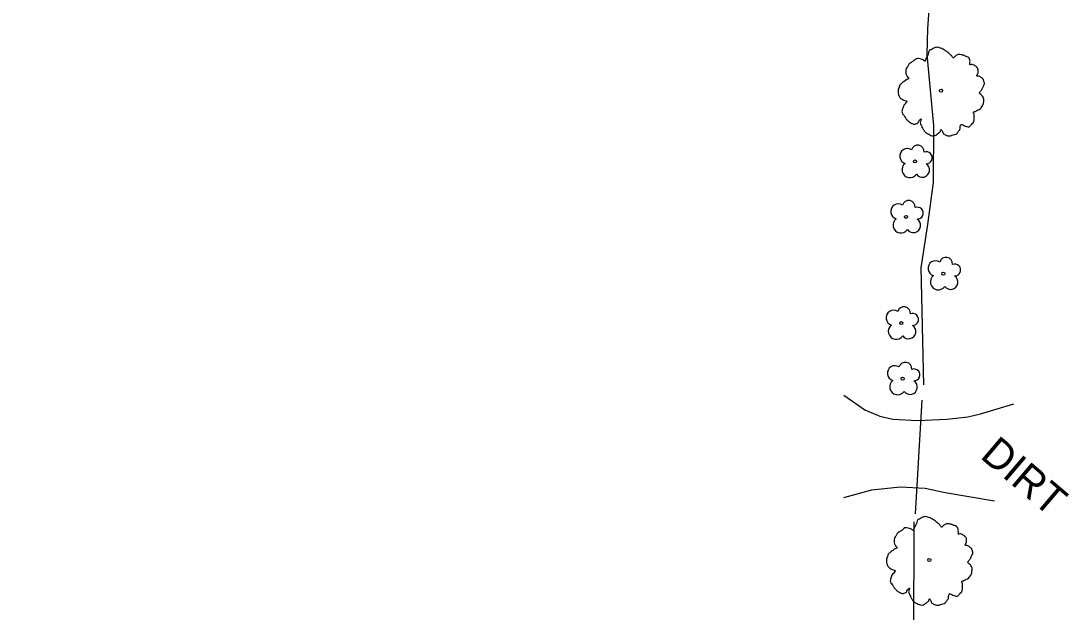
# Model space of a CAD drawing. Extents: x 2076109 to 2080761, y 592812 to 596750.
# Drawn here: x 2076804.3 to 2076979, y 595772.6 to 595871.1 of the extents above; entities that cross this region are included whole.
import ezdxf

# ---------------------------------------------------------------- set-up
doc = ezdxf.new("R2010")
doc.units = 0
for name, color, linetype in [('RD_EX_DR_Pipe', 7, 'Continuous'), ('RD_EX_Driveway', 7, 'Continuous'), ('RD_EX_Driveway_txCode', 7, 'Continuous'), ('RD_EX_H2O', 7, 'Continuous'), ('RD_EX_VEG', 7, 'Continuous')]:
    doc.layers.add(name, color=color, linetype=linetype)

msp = doc.modelspace()

# ---------------------------------------------------------------- linework, layer by layer
at = {"layer": 'RD_EX_DR_Pipe'}
msp.add_line((2076954.49, 595807.87), (2076953.41, 595788.91), dxfattribs=at)
msp.add_line((2076954.49, 595807.87), (2076953.41, 595788.91), dxfattribs=at)
at = {"layer": 'RD_EX_Driveway'}
for points in [[(2076941.49, 595808.73), (2076944.98, 595806.27), (2076947.48, 595805.2), (2076949.66, 595804.73), (2076953.82, 595804.47), (2076958.66, 595804.69), (2076962.15, 595805.1), (2076964.3, 595805.62), (2076969.85, 595807.26)], [(2076941.49, 595808.73), (2076944.98, 595806.27), (2076947.48, 595805.2), (2076949.66, 595804.73), (2076953.82, 595804.47), (2076958.66, 595804.69), (2076962.15, 595805.1), (2076964.3, 595805.62), (2076969.85, 595807.26)], [(2076941.5, 595791.66), (2076946.18, 595792.94), (2076950.88, 595793.42), (2076955.05, 595793.23), (2076958.38, 595792.48), (2076966.62, 595791.1)], [(2076941.5, 595791.66), (2076946.18, 595792.94), (2076950.88, 595793.42), (2076955.05, 595793.23), (2076958.38, 595792.48), (2076966.62, 595791.1)]]:
    msp.add_lwpolyline(points, dxfattribs=at)
at = {"layer": 'RD_EX_H2O'}
for points in [[(2076956.27, 595881.28), (2076955.47, 595869.82), (2076955.32, 595865.52), (2076956.46, 595853.67), (2076956.38, 595844.15), (2076955.42, 595837.17), (2076954.34, 595829.92), (2076954.75, 595810.44)], [(2076956.27, 595881.28), (2076955.47, 595869.82), (2076955.32, 595865.52), (2076956.46, 595853.67), (2076956.38, 595844.15), (2076955.42, 595837.17), (2076954.34, 595829.92), (2076954.75, 595810.44)], [(2076953.18, 595787.61), (2076953.11, 595768.11), (2076952.56, 595756.13), (2076952.64, 595748.41), (2076952.76, 595745.08), (2076953.8, 595742.99), (2076953.36, 595730.22), (2076953.03, 595725.71), (2076951.39, 595721.38), (2076949.37, 595718.3), (2076942.5, 595711.04), (2076932.67, 595698.19), (2076918.85, 595680.89), (2076905.91, 595664.86), (2076891.97, 595647.71), (2076883.67, 595637.84), (2076877.03, 595627.21), (2076865.95, 595614.44), (2076853.87, 595600.18), (2076844.92, 595587.87), (2076832.87, 595574.13), (2076822.92, 595563.08), (2076804.28, 595545.77)], [(2076953.18, 595787.61), (2076953.11, 595768.11), (2076952.56, 595756.13), (2076952.64, 595748.41), (2076952.76, 595745.08), (2076953.8, 595742.99), (2076953.36, 595730.22), (2076953.03, 595725.71), (2076951.39, 595721.38), (2076949.37, 595718.3), (2076942.5, 595711.04), (2076932.67, 595698.19), (2076918.85, 595680.89), (2076905.91, 595664.86), (2076891.97, 595647.71), (2076883.67, 595637.84), (2076877.03, 595627.21), (2076865.95, 595614.44), (2076853.87, 595600.18), (2076844.92, 595587.87), (2076832.87, 595574.13), (2076822.92, 595563.08), (2076804.28, 595545.77)]]:
    msp.add_lwpolyline(points, dxfattribs=at)
at = {"layer": 'RD_EX_VEG'}
for centre, radius in [((2076957.7, 595859.47), 0.25), ((2076957.7, 595859.47), 0.25), ((2076957.67, 595859.46), 0.0001), ((2076957.67, 595859.46), 0.0001), ((2076953.36, 595847.67), 0.25), ((2076953.36, 595847.67), 0.25), ((2076951.86, 595838.43), 0.25), ((2076951.86, 595838.43), 0.25), ((2076958.08, 595828.96), 0.25), ((2076958.08, 595828.96), 0.25), ((2076951.07, 595820.72), 0.25), ((2076951.07, 595820.72), 0.25), ((2076951.3, 595811.47), 0.25), ((2076951.3, 595811.47), 0.25), ((2076955.75, 595781.24), 0.25), ((2076955.75, 595781.24), 0.25), ((2076955.73, 595781.24), 0.0001), ((2076955.73, 595781.24), 0.0001)]:
    msp.add_circle(centre, radius, dxfattribs=at)
for centre, radius, start, end in [((2076952.06, 595848.56), 1.26, 56.0792, 254.3614), ((2076952.06, 595848.56), 1.26, 56.0792, 254.3614), ((2076953.81, 595849.31), 1.08, 354.6037, 164.3834), ((2076953.81, 595849.31), 1.08, 354.6037, 164.3834), ((2076955.25, 595848.29), 0.995, 268.39, 111.6741), ((2076955.25, 595848.29), 0.995, 268.39, 111.6741), ((2076952.51, 595846.29), 1.32, 126.51, 325.3863), ((2076952.51, 595846.29), 1.32, 126.51, 325.3863), ((2076954.58, 595846.26), 1.22, 216.1941, 57.732), ((2076954.58, 595846.26), 1.22, 216.1941, 57.732), ((2076950.57, 595839.33), 1.26, 56.0792, 254.3614), ((2076950.57, 595839.33), 1.26, 56.0792, 254.3614), ((2076952.31, 595840.08), 1.08, 354.6037, 164.3834), ((2076952.31, 595840.08), 1.08, 354.6037, 164.3834), ((2076953.76, 595839.05), 0.995, 268.39, 111.6741), ((2076953.76, 595839.05), 0.995, 268.39, 111.6741), ((2076951.01, 595837.06), 1.32, 126.51, 325.3863), ((2076951.01, 595837.06), 1.32, 126.51, 325.3863), ((2076953.08, 595837.03), 1.22, 216.1941, 57.732), ((2076953.08, 595837.03), 1.22, 216.1941, 57.732), ((2076956.79, 595829.86), 1.26, 56.0792, 254.3614), ((2076956.79, 595829.86), 1.26, 56.0792, 254.3614), ((2076958.54, 595830.61), 1.08, 354.6037, 164.3834), ((2076958.54, 595830.61), 1.08, 354.6037, 164.3834), ((2076959.98, 595829.58), 0.995, 268.39, 111.6741), ((2076959.98, 595829.58), 0.995, 268.39, 111.6741), ((2076957.24, 595827.59), 1.32, 126.51, 325.3863), ((2076957.24, 595827.59), 1.32, 126.51, 325.3863), ((2076959.3, 595827.56), 1.22, 216.1941, 57.732), ((2076959.3, 595827.56), 1.22, 216.1941, 57.732), ((2076951.53, 595822.37), 1.08, 354.6037, 164.3834), ((2076951.53, 595822.37), 1.08, 354.6037, 164.3834), ((2076949.78, 595821.61), 1.26, 56.0792, 254.3614), ((2076949.78, 595821.61), 1.26, 56.0792, 254.3614), ((2076952.97, 595821.34), 0.995, 268.39, 111.6741), ((2076952.97, 595821.34), 0.995, 268.39, 111.6741), ((2076950.23, 595819.34), 1.32, 126.51, 325.3863), ((2076950.23, 595819.34), 1.32, 126.51, 325.3863), ((2076952.29, 595819.32), 1.22, 216.1941, 57.732), ((2076952.29, 595819.32), 1.22, 216.1941, 57.732), ((2076950.01, 595812.37), 1.26, 56.0792, 254.3614), ((2076950.01, 595812.37), 1.26, 56.0792, 254.3614), ((2076951.76, 595813.12), 1.08, 354.6037, 164.3834), ((2076951.76, 595813.12), 1.08, 354.6037, 164.3834), ((2076953.2, 595812.09), 0.995, 268.39, 111.6741), ((2076953.2, 595812.09), 0.995, 268.39, 111.6741), ((2076950.46, 595810.1), 1.32, 126.51, 325.3863), ((2076950.46, 595810.1), 1.32, 126.51, 325.3863), ((2076952.53, 595810.07), 1.22, 216.1941, 57.732), ((2076952.53, 595810.07), 1.22, 216.1941, 57.732)]:
    msp.add_arc(centre, radius, start, end, dxfattribs=at)
for points in [[(2076962.44, 595864.84), (2076962.23, 595865.06), (2076961.91, 595865.19), (2076961.66, 595865.28), (2076961.44, 595865.36), (2076961.2, 595865.43), (2076960.86, 595865.49), (2076960.56, 595865.49), (2076960.3, 595865.38), (2076960.12, 595865.24), (2076959.9, 595865.06), (2076959.79, 595864.93), (2076959.68, 595864.99), (2076959.58, 595865.11), (2076959.44, 595865.33), (2076959.25, 595865.49), (2076959.06, 595865.65), (2076958.78, 595865.86), (2076958.51, 595866.08), (2076958.27, 595866.22), (2076957.99, 595866.4), (2076957.62, 595866.54), (2076957.27, 595866.68), (2076956.88, 595866.68), (2076956.39, 595866.48), (2076956.06, 595866.29), (2076955.79, 595866.2), (2076955.61, 595865.76), (2076955.52, 595865.38), (2076955.41, 595865.21), (2076955.19, 595864.84), (2076955.12, 595864.6), (2076955.08, 595864.37), (2076955.01, 595864.4), (2076954.69, 595864.61), (2076954.4, 595864.72), (2076953.93, 595864.83), (2076953.61, 595864.8), (2076953.33, 595864.62), (2076953.08, 595864.37), (2076952.88, 595864.28), (2076952.64, 595864.12), (2076952.57, 595864.08), (2076952.32, 595863.86), (2076952.11, 595863.46), (2076951.9, 595863.17), (2076951.85, 595862.92), (2076951.85, 595862.69), (2076951.82, 595862.39), (2076951.98, 595861.96), (2076952.17, 595861.67), (2076952.3, 595861.52), (2076951.84, 595861.25), (2076951.58, 595861.02), (2076951.23, 595860.8), (2076951.18, 595860.74), (2076950.83, 595860.41), (2076950.74, 595860.07), (2076950.55, 595859.73), (2076950.54, 595859.45), (2076950.55, 595859.04), (2076950.65, 595858.66), (2076950.95, 595858.24), (2076951.28, 595858), (2076951.83, 595857.76), (2076952.07, 595857.66), (2076951.93, 595857.54), (2076951.71, 595857.24), (2076951.43, 595856.91), (2076951.34, 595856.57), (2076951.24, 595856.29), (2076951.19, 595856.01), (2076951.29, 595855.63), (2076951.55, 595855.31), (2076951.77, 595854.92), (2076952.07, 595854.57), (2076952.43, 595854.23), (2076952.99, 595853.95), (2076953.28, 595853.87), (2076953.47, 595853.94), (2076953.86, 595854.1), (2076953.97, 595854.3), (2076954.38, 595854.74), (2076954.34, 595854.54), (2076954.24, 595854.16), (2076954.43, 595853.61), (2076954.62, 595853.22), (2076954.89, 595852.8), (2076955.07, 595852.55), (2076955.48, 595852.29), (2076955.81, 595852.11), (2076956.18, 595851.96), (2076956.58, 595851.98), (2076956.9, 595852.07), (2076957.11, 595852.25), (2076957.41, 595852.49), (2076957.56, 595852.59)], [(2076962.44, 595864.84), (2076962.23, 595865.06), (2076961.91, 595865.19), (2076961.66, 595865.28), (2076961.44, 595865.36), (2076961.2, 595865.43), (2076960.86, 595865.49), (2076960.56, 595865.49), (2076960.3, 595865.38), (2076960.12, 595865.24), (2076959.9, 595865.06), (2076959.79, 595864.93), (2076959.68, 595864.99), (2076959.58, 595865.11), (2076959.44, 595865.33), (2076959.25, 595865.49), (2076959.06, 595865.65), (2076958.78, 595865.86), (2076958.51, 595866.08), (2076958.27, 595866.22), (2076957.99, 595866.4), (2076957.62, 595866.54), (2076957.27, 595866.68), (2076956.88, 595866.68), (2076956.39, 595866.48), (2076956.06, 595866.29), (2076955.79, 595866.2), (2076955.61, 595865.76), (2076955.52, 595865.38), (2076955.41, 595865.21), (2076955.19, 595864.84), (2076955.12, 595864.6), (2076955.08, 595864.37), (2076955.01, 595864.4), (2076954.69, 595864.61), (2076954.4, 595864.72), (2076953.93, 595864.83), (2076953.61, 595864.8), (2076953.33, 595864.62), (2076953.08, 595864.37), (2076952.88, 595864.28), (2076952.64, 595864.12), (2076952.57, 595864.08), (2076952.32, 595863.86), (2076952.11, 595863.46), (2076951.9, 595863.17), (2076951.85, 595862.92), (2076951.85, 595862.69), (2076951.82, 595862.39), (2076951.98, 595861.96), (2076952.17, 595861.67), (2076952.3, 595861.52), (2076951.84, 595861.25), (2076951.58, 595861.02), (2076951.23, 595860.8), (2076951.18, 595860.74), (2076950.83, 595860.41), (2076950.74, 595860.07), (2076950.55, 595859.73), (2076950.54, 595859.45), (2076950.55, 595859.04), (2076950.65, 595858.66), (2076950.95, 595858.24), (2076951.28, 595858), (2076951.83, 595857.76), (2076952.07, 595857.66), (2076951.93, 595857.54), (2076951.71, 595857.24), (2076951.43, 595856.91), (2076951.34, 595856.57), (2076951.24, 595856.29), (2076951.19, 595856.01), (2076951.29, 595855.63), (2076951.55, 595855.31), (2076951.77, 595854.92), (2076952.07, 595854.57), (2076952.43, 595854.23), (2076952.99, 595853.95), (2076953.28, 595853.87), (2076953.47, 595853.94), (2076953.86, 595854.1), (2076953.97, 595854.3), (2076954.38, 595854.74), (2076954.34, 595854.54), (2076954.24, 595854.16), (2076954.43, 595853.61), (2076954.62, 595853.22), (2076954.89, 595852.8), (2076955.07, 595852.55), (2076955.48, 595852.29), (2076955.81, 595852.11), (2076956.18, 595851.96), (2076956.58, 595851.98), (2076956.9, 595852.07), (2076957.11, 595852.25), (2076957.41, 595852.49), (2076957.56, 595852.59)], [(2076957.56, 595852.59), (2076957.62, 595852.77), (2076957.74, 595852.99), (2076957.78, 595852.92), (2076957.89, 595852.77), (2076958.01, 595852.5), (2076958.14, 595852.3), (2076958.4, 595852.11), (2076958.67, 595852), (2076959.19, 595851.92), (2076959.71, 595852.11), (2076960.18, 595852.23), (2076960.45, 595852.43), (2076960.56, 595852.63), (2076960.86, 595853.03), (2076960.87, 595853.35), (2076960.91, 595853.48), (2076961.1, 595853.85), (2076961.18, 595853.84), (2076961.43, 595853.7), (2076961.79, 595853.55), (2076962.08, 595853.47), (2076962.37, 595853.46), (2076962.57, 595853.58), (2076962.81, 595853.9), (2076963.11, 595854.17), (2076963.15, 595854.33), (2076963.17, 595854.51), (2076963.24, 595854.71), (2076963.22, 595854.92), (2076963.25, 595855.1), (2076963.23, 595855.24), (2076963.24, 595855.44), (2076963.18, 595855.65), (2076963.1, 595855.78), (2076963.16, 595855.93), (2076963.4, 595855.99), (2076963.51, 595856.03), (2076963.67, 595856.18), (2076964.07, 595856.31), (2076964.37, 595856.58), (2076964.6, 595856.93), (2076964.74, 595857.18), (2076964.81, 595857.48), (2076964.82, 595857.8), (2076964.84, 595858.02), (2076964.78, 595858.22), (2076964.62, 595858.53), (2076964.46, 595858.73), (2076964.19, 595858.96), (2076964.07, 595859.12), (2076964.12, 595859.15), (2076964.22, 595859.26), (2076964.4, 595859.47), (2076964.63, 595859.86), (2076964.84, 595860.34), (2076964.86, 595860.36), (2076964.94, 595860.61), (2076964.9, 595860.91), (2076964.83, 595861.1), (2076964.76, 595861.33), (2076964.59, 595861.51), (2076964.36, 595861.7), (2076964.12, 595861.84), (2076963.9, 595861.89), (2076963.69, 595861.91), (2076963.73, 595862.07), (2076963.85, 595862.37), (2076963.9, 595862.51), (2076963.9, 595862.74), (2076963.86, 595863.04), (2076963.6, 595863.43), (2076963.08, 595863.78), (2076962.72, 595863.82), (2076962.49, 595863.78), (2076962.53, 595863.91), (2076962.51, 595864.19), (2076962.55, 595864.39), (2076962.49, 595864.6), (2076962.44, 595864.77), (2076962.4, 595864.87)], [(2076957.56, 595852.59), (2076957.62, 595852.77), (2076957.74, 595852.99), (2076957.78, 595852.92), (2076957.89, 595852.77), (2076958.01, 595852.5), (2076958.14, 595852.3), (2076958.4, 595852.11), (2076958.67, 595852), (2076959.19, 595851.92), (2076959.71, 595852.11), (2076960.18, 595852.23), (2076960.45, 595852.43), (2076960.56, 595852.63), (2076960.86, 595853.03), (2076960.87, 595853.35), (2076960.91, 595853.48), (2076961.1, 595853.85), (2076961.18, 595853.84), (2076961.43, 595853.7), (2076961.79, 595853.55), (2076962.08, 595853.47), (2076962.37, 595853.46), (2076962.57, 595853.58), (2076962.81, 595853.9), (2076963.11, 595854.17), (2076963.15, 595854.33), (2076963.17, 595854.51), (2076963.24, 595854.71), (2076963.22, 595854.92), (2076963.25, 595855.1), (2076963.23, 595855.24), (2076963.24, 595855.44), (2076963.18, 595855.65), (2076963.1, 595855.78), (2076963.16, 595855.93), (2076963.4, 595855.99), (2076963.51, 595856.03), (2076963.67, 595856.18), (2076964.07, 595856.31), (2076964.37, 595856.58), (2076964.6, 595856.93), (2076964.74, 595857.18), (2076964.81, 595857.48), (2076964.82, 595857.8), (2076964.84, 595858.02), (2076964.78, 595858.22), (2076964.62, 595858.53), (2076964.46, 595858.73), (2076964.19, 595858.96), (2076964.07, 595859.12), (2076964.12, 595859.15), (2076964.22, 595859.26), (2076964.4, 595859.47), (2076964.63, 595859.86), (2076964.84, 595860.34), (2076964.86, 595860.36), (2076964.94, 595860.61), (2076964.9, 595860.91), (2076964.83, 595861.1), (2076964.76, 595861.33), (2076964.59, 595861.51), (2076964.36, 595861.7), (2076964.12, 595861.84), (2076963.9, 595861.89), (2076963.69, 595861.91), (2076963.73, 595862.07), (2076963.85, 595862.37), (2076963.9, 595862.51), (2076963.9, 595862.74), (2076963.86, 595863.04), (2076963.6, 595863.43), (2076963.08, 595863.78), (2076962.72, 595863.82), (2076962.49, 595863.78), (2076962.53, 595863.91), (2076962.51, 595864.19), (2076962.55, 595864.39), (2076962.49, 595864.6), (2076962.44, 595864.77), (2076962.4, 595864.87)], [(2076960.5, 595786.62), (2076960.28, 595786.83), (2076959.97, 595786.97), (2076959.72, 595787.05), (2076959.5, 595787.14), (2076959.26, 595787.21), (2076958.92, 595787.27), (2076958.62, 595787.26), (2076958.36, 595787.16), (2076958.18, 595787.02), (2076957.96, 595786.84), (2076957.85, 595786.71), (2076957.74, 595786.77), (2076957.64, 595786.88), (2076957.5, 595787.1), (2076957.31, 595787.26), (2076957.11, 595787.43), (2076956.83, 595787.63), (2076956.57, 595787.86), (2076956.32, 595788), (2076956.04, 595788.17), (2076955.68, 595788.32), (2076955.33, 595788.45), (2076954.94, 595788.46), (2076954.44, 595788.26), (2076954.12, 595788.07), (2076953.84, 595787.98), (2076953.67, 595787.54), (2076953.57, 595787.16), (2076953.46, 595786.99), (2076953.24, 595786.62), (2076953.18, 595786.38), (2076953.14, 595786.15), (2076953.07, 595786.18), (2076952.75, 595786.38), (2076952.46, 595786.5), (2076951.99, 595786.6), (2076951.67, 595786.58), (2076951.38, 595786.4), (2076951.14, 595786.15), (2076950.93, 595786.06), (2076950.7, 595785.9), (2076950.63, 595785.86), (2076950.38, 595785.64), (2076950.17, 595785.23), (2076949.96, 595784.95), (2076949.91, 595784.7), (2076949.91, 595784.47), (2076949.88, 595784.16), (2076950.04, 595783.73), (2076950.22, 595783.45), (2076950.36, 595783.3), (2076949.9, 595783.03), (2076949.64, 595782.8), (2076949.28, 595782.57), (2076949.23, 595782.52), (2076948.89, 595782.19), (2076948.79, 595781.84), (2076948.61, 595781.51), (2076948.59, 595781.22), (2076948.61, 595780.82), (2076948.71, 595780.44), (2076949.01, 595780.02), (2076949.33, 595779.78), (2076949.88, 595779.54), (2076950.12, 595779.43), (2076949.99, 595779.32), (2076949.77, 595779.01), (2076949.49, 595778.69), (2076949.39, 595778.35), (2076949.29, 595778.07), (2076949.24, 595777.78), (2076949.35, 595777.4), (2076949.6, 595777.09), (2076949.83, 595776.7), (2076950.12, 595776.35), (2076950.49, 595776.01), (2076951.04, 595775.73), (2076951.33, 595775.65), (2076951.52, 595775.72), (2076951.92, 595775.87), (2076952.02, 595776.08), (2076952.43, 595776.52), (2076952.39, 595776.32), (2076952.3, 595775.94), (2076952.49, 595775.39), (2076952.68, 595775), (2076952.94, 595774.57), (2076953.12, 595774.32), (2076953.53, 595774.07), (2076953.87, 595773.89), (2076954.23, 595773.74), (2076954.64, 595773.75), (2076954.95, 595773.85), (2076955.17, 595774.03), (2076955.47, 595774.26), (2076955.62, 595774.36)], [(2076960.5, 595786.62), (2076960.28, 595786.83), (2076959.97, 595786.97), (2076959.72, 595787.05), (2076959.5, 595787.14), (2076959.26, 595787.21), (2076958.92, 595787.27), (2076958.62, 595787.26), (2076958.36, 595787.16), (2076958.18, 595787.02), (2076957.96, 595786.84), (2076957.85, 595786.71), (2076957.74, 595786.77), (2076957.64, 595786.88), (2076957.5, 595787.1), (2076957.31, 595787.26), (2076957.11, 595787.43), (2076956.83, 595787.63), (2076956.57, 595787.86), (2076956.32, 595788), (2076956.04, 595788.17), (2076955.68, 595788.32), (2076955.33, 595788.45), (2076954.94, 595788.46), (2076954.44, 595788.26), (2076954.12, 595788.07), (2076953.84, 595787.98), (2076953.67, 595787.54), (2076953.57, 595787.16), (2076953.46, 595786.99), (2076953.24, 595786.62), (2076953.18, 595786.38), (2076953.14, 595786.15), (2076953.07, 595786.18), (2076952.75, 595786.38), (2076952.46, 595786.5), (2076951.99, 595786.6), (2076951.67, 595786.58), (2076951.38, 595786.4), (2076951.14, 595786.15), (2076950.93, 595786.06), (2076950.7, 595785.9), (2076950.63, 595785.86), (2076950.38, 595785.64), (2076950.17, 595785.23), (2076949.96, 595784.95), (2076949.91, 595784.7), (2076949.91, 595784.47), (2076949.88, 595784.16), (2076950.04, 595783.73), (2076950.22, 595783.45), (2076950.36, 595783.3), (2076949.9, 595783.03), (2076949.64, 595782.8), (2076949.28, 595782.57), (2076949.23, 595782.52), (2076948.89, 595782.19), (2076948.79, 595781.84), (2076948.61, 595781.51), (2076948.59, 595781.22), (2076948.61, 595780.82), (2076948.71, 595780.44), (2076949.01, 595780.02), (2076949.33, 595779.78), (2076949.88, 595779.54), (2076950.12, 595779.43), (2076949.99, 595779.32), (2076949.77, 595779.01), (2076949.49, 595778.69), (2076949.39, 595778.35), (2076949.29, 595778.07), (2076949.24, 595777.78), (2076949.35, 595777.4), (2076949.6, 595777.09), (2076949.83, 595776.7), (2076950.12, 595776.35), (2076950.49, 595776.01), (2076951.04, 595775.73), (2076951.33, 595775.65), (2076951.52, 595775.72), (2076951.92, 595775.87), (2076952.02, 595776.08), (2076952.43, 595776.52), (2076952.39, 595776.32), (2076952.3, 595775.94), (2076952.49, 595775.39), (2076952.68, 595775), (2076952.94, 595774.57), (2076953.12, 595774.32), (2076953.53, 595774.07), (2076953.87, 595773.89), (2076954.23, 595773.74), (2076954.64, 595773.75), (2076954.95, 595773.85), (2076955.17, 595774.03), (2076955.47, 595774.26), (2076955.62, 595774.36)], [(2076955.62, 595774.36), (2076955.68, 595774.55), (2076955.8, 595774.77), (2076955.84, 595774.7), (2076955.94, 595774.55), (2076956.07, 595774.28), (2076956.19, 595774.07), (2076956.46, 595773.88), (2076956.73, 595773.78), (2076957.25, 595773.7), (2076957.77, 595773.88), (2076958.24, 595774.01), (2076958.5, 595774.21), (2076958.61, 595774.41), (2076958.92, 595774.81), (2076958.93, 595775.13), (2076958.97, 595775.26), (2076959.15, 595775.63), (2076959.24, 595775.61), (2076959.48, 595775.47), (2076959.85, 595775.33), (2076960.14, 595775.24), (2076960.42, 595775.23), (2076960.63, 595775.35), (2076960.87, 595775.68), (2076961.16, 595775.95), (2076961.2, 595776.11), (2076961.23, 595776.29), (2076961.3, 595776.49), (2076961.28, 595776.7), (2076961.3, 595776.88), (2076961.29, 595777.02), (2076961.29, 595777.22), (2076961.24, 595777.43), (2076961.16, 595777.56), (2076961.22, 595777.71), (2076961.46, 595777.76), (2076961.56, 595777.81), (2076961.73, 595777.96), (2076962.13, 595778.08), (2076962.42, 595778.35), (2076962.66, 595778.71), (2076962.8, 595778.95), (2076962.86, 595779.26), (2076962.87, 595779.58), (2076962.89, 595779.79), (2076962.84, 595780), (2076962.67, 595780.31), (2076962.51, 595780.51), (2076962.25, 595780.73), (2076962.13, 595780.9), (2076962.18, 595780.92), (2076962.28, 595781.04), (2076962.45, 595781.25), (2076962.69, 595781.64), (2076962.9, 595782.12), (2076962.91, 595782.13), (2076963, 595782.39), (2076962.96, 595782.69), (2076962.89, 595782.88), (2076962.82, 595783.1), (2076962.64, 595783.28), (2076962.42, 595783.48), (2076962.17, 595783.62), (2076961.96, 595783.67), (2076961.74, 595783.69), (2076961.78, 595783.85), (2076961.9, 595784.14), (2076961.96, 595784.29), (2076961.96, 595784.52), (2076961.92, 595784.82), (2076961.66, 595785.21), (2076961.13, 595785.55), (2076960.77, 595785.6), (2076960.55, 595785.56), (2076960.59, 595785.69), (2076960.57, 595785.97), (2076960.6, 595786.17), (2076960.55, 595786.38), (2076960.5, 595786.55), (2076960.46, 595786.65)], [(2076955.62, 595774.36), (2076955.68, 595774.55), (2076955.8, 595774.77), (2076955.84, 595774.7), (2076955.94, 595774.55), (2076956.07, 595774.28), (2076956.19, 595774.07), (2076956.46, 595773.88), (2076956.73, 595773.78), (2076957.25, 595773.7), (2076957.77, 595773.88), (2076958.24, 595774.01), (2076958.5, 595774.21), (2076958.61, 595774.41), (2076958.92, 595774.81), (2076958.93, 595775.13), (2076958.97, 595775.26), (2076959.15, 595775.63), (2076959.24, 595775.61), (2076959.48, 595775.47), (2076959.85, 595775.33), (2076960.14, 595775.24), (2076960.42, 595775.23), (2076960.63, 595775.35), (2076960.87, 595775.68), (2076961.16, 595775.95), (2076961.2, 595776.11), (2076961.23, 595776.29), (2076961.3, 595776.49), (2076961.28, 595776.7), (2076961.3, 595776.88), (2076961.29, 595777.02), (2076961.29, 595777.22), (2076961.24, 595777.43), (2076961.16, 595777.56), (2076961.22, 595777.71), (2076961.46, 595777.76), (2076961.56, 595777.81), (2076961.73, 595777.96), (2076962.13, 595778.08), (2076962.42, 595778.35), (2076962.66, 595778.71), (2076962.8, 595778.95), (2076962.86, 595779.26), (2076962.87, 595779.58), (2076962.89, 595779.79), (2076962.84, 595780), (2076962.67, 595780.31), (2076962.51, 595780.51), (2076962.25, 595780.73), (2076962.13, 595780.9), (2076962.18, 595780.92), (2076962.28, 595781.04), (2076962.45, 595781.25), (2076962.69, 595781.64), (2076962.9, 595782.12), (2076962.91, 595782.13), (2076963, 595782.39), (2076962.96, 595782.69), (2076962.89, 595782.88), (2076962.82, 595783.1), (2076962.64, 595783.28), (2076962.42, 595783.48), (2076962.17, 595783.62), (2076961.96, 595783.67), (2076961.74, 595783.69), (2076961.78, 595783.85), (2076961.9, 595784.14), (2076961.96, 595784.29), (2076961.96, 595784.52), (2076961.92, 595784.82), (2076961.66, 595785.21), (2076961.13, 595785.55), (2076960.77, 595785.6), (2076960.55, 595785.56), (2076960.59, 595785.69), (2076960.57, 595785.97), (2076960.6, 595786.17), (2076960.55, 595786.38), (2076960.5, 595786.55), (2076960.46, 595786.65)]]:
    msp.add_spline(points, degree=3, dxfattribs=at)

# ---------------------------------------------------------------- texts
at = {"layer": 'RD_EX_Driveway_txCode'}
msp.add_text('DIRT', height=5, rotation=319.6274, dxfattribs=at).set_placement((2076964.04, 595798.37))
msp.add_text('DIRT', height=5, rotation=319.6274, dxfattribs=at).set_placement((2076964.04, 595798.37))

doc.saveas('drawing.dxf')
